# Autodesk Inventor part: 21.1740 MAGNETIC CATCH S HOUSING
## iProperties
Created: 2007-03
Part Number: 21.1740 MAGNETIC CATCH S HOUSING
Material: ABS Plastic
Document SubType Name: Modeling
Designer: Andy Moles
Density: 1.06 g/cm^3
Author: Andy Moles
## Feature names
1. Extrusion1
2. Extrusion2
3. Extrusion3
4. Hole1
5. Hole2
6. Hole3
7. Hole4
8. Extrusion4
9. Extrusion5
10. Fillet1
11. Extrusion6
12. Extrusion7
13. Extrusion8
